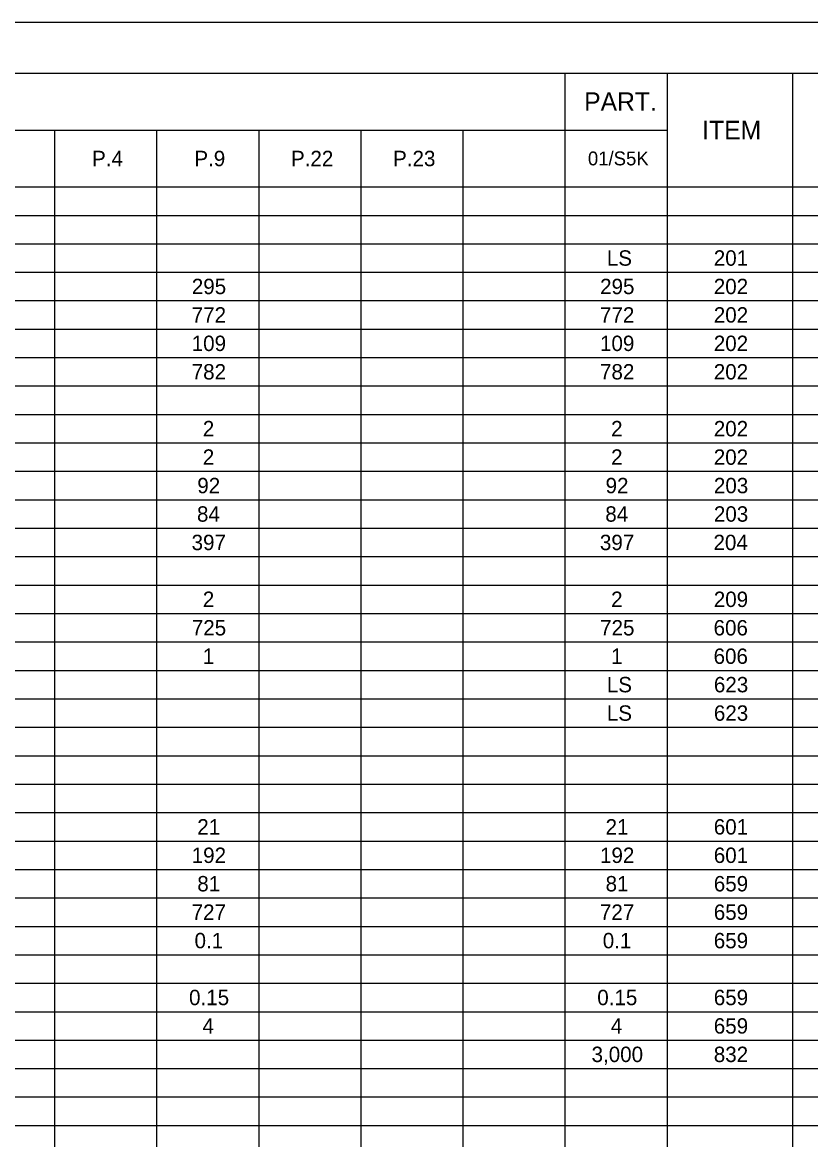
# Model space of a CAD drawing. Extents: x 0 to 34, y 0 to 22.
# Drawn here: x 9.22 to 16.98, y 11 to 22 of the extents above; entities that cross this region are included whole.
import ezdxf

# ---------------------------------------------------------------- set-up
doc = ezdxf.new("R2010")
doc.units = 0
for name, color, linetype in [('Default', 7, 'Continuous'), ('SH_Border', 7, 'Continuous'), ('SH_Cut_Line', 7, 'Continuous')]:
    doc.layers.add(name, color=color, linetype=linetype)

msp = doc.modelspace()

# ---------------------------------------------------------------- linework, layer by layer
at = {"layer": 'Default'}
for p, q in [((1.5, 21.5), (32.004, 21.5)), ((14.561, 21.5), (14.561, 0.5)), ((15.566, 21.5), (15.566, 0.5)), ((16.801, 21.5), (16.801, 0.5)), ((1.5, 20.94), (15.566, 20.94)), ((9.538, 20.94), (9.538, 0.5)), ((10.542, 20.94), (10.542, 0.5)), ((11.547, 20.94), (11.547, 0.5)), ((12.552, 20.94), (12.552, 0.5)), ((13.556, 20.94), (13.556, 0.5)), ((1.5, 20.38), (32.004, 20.38)), ((1.5, 20.1), (32.004, 20.1)), ((1.5, 19.82), (32.004, 19.82)), ((1.5, 19.54), (32.004, 19.54)), ((1.5, 19.26), (32.004, 19.26)), ((1.5, 18.98), (32.004, 18.98)), ((1.5, 18.7), (32.004, 18.7)), ((1.5, 18.42), (32.004, 18.42)), ((1.5, 18.14), (32.004, 18.14)), ((1.5, 17.86), (32.004, 17.86)), ((1.5, 17.58), (32.004, 17.58)), ((1.5, 17.3), (32.004, 17.3)), ((1.5, 17.02), (32.004, 17.02)), ((1.5, 16.74), (32.004, 16.74)), ((1.5, 16.46), (32.004, 16.46)), ((1.5, 16.18), (32.004, 16.18)), ((1.5, 15.9), (32.004, 15.9)), ((1.5, 15.62), (32.004, 15.62)), ((1.5, 15.34), (32.004, 15.34)), ((1.5, 15.06), (32.004, 15.06)), ((1.5, 14.78), (32.004, 14.78)), ((1.5, 14.5), (32.004, 14.5)), ((1.5, 14.22), (32.004, 14.22)), ((1.5, 13.94), (32.004, 13.94)), ((1.5, 13.66), (32.004, 13.66)), ((1.5, 13.38), (32.004, 13.38)), ((1.5, 13.1), (32.004, 13.1)), ((1.5, 12.82), (32.004, 12.82)), ((1.5, 12.54), (32.004, 12.54)), ((1.5, 12.26), (32.004, 12.26)), ((1.5, 11.98), (32.004, 11.98)), ((1.5, 11.7), (32.004, 11.7)), ((1.5, 11.42), (32.004, 11.42)), ((1.5, 11.14), (32.004, 11.14))]:
    msp.add_line(p, q, dxfattribs=at)
at = {"layer": 'SH_Border'}
msp.add_lwpolyline([(1.5, 21.5), (33.5, 21.5), (33.5, 0.5), (1.5, 0.5)], close=True, dxfattribs=at)
at = {"layer": 'SH_Cut_Line'}
msp.add_lwpolyline([(0, 0), (34, 0), (34, 22), (0, 22)], close=True, dxfattribs=at)

# ---------------------------------------------------------------- texts
at = {"layer": 'Default'}
for s, height, p in [('PART.', 0.1818, (14.75, 21.129)), ('ITEM', 0.1818, (15.912, 20.849)), ('P.4', 0.1515, (9.906, 20.584)), ('P.9', 0.1515, (10.913, 20.584)), ('P.22', 0.1515, (11.864, 20.584)), ('P.23', 0.1515, (12.869, 20.584)), ('01/S5K', 0.1364, (14.787, 20.592)), ('LS', 0.1515, (14.973, 19.604)), ('201', 0.1515, (16.026, 19.604)), ('295', 0.1515, (10.888, 19.324)), ('295', 0.1515, (14.907, 19.324)), ('202', 0.1515, (16.026, 19.324)), ('772', 0.1515, (10.887, 19.044)), ('772', 0.1515, (14.906, 19.044)), ('202', 0.1515, (16.026, 19.044)), ('109', 0.1515, (10.887, 18.764)), ('109', 0.1515, (14.906, 18.764)), ('202', 0.1515, (16.026, 18.764)), ('782', 0.1515, (10.887, 18.484)), ('782', 0.1515, (14.906, 18.484)), ('202', 0.1515, (16.026, 18.484)), ('2', 0.152, (10.996, 17.924)), ('2', 0.152, (15.015, 17.924)), ('202', 0.1515, (16.026, 17.924)), ('2', 0.152, (10.996, 17.644)), ('2', 0.152, (15.015, 17.644)), ('202', 0.1515, (16.026, 17.644)), ('92', 0.1515, (10.942, 17.364)), ('92', 0.1515, (14.961, 17.364)), ('203', 0.1515, (16.027, 17.364)), ('84', 0.1515, (10.939, 17.084)), ('84', 0.1515, (14.958, 17.084)), ('203', 0.1515, (16.027, 17.084)), ('397', 0.1515, (10.886, 16.804)), ('397', 0.1515, (14.905, 16.804)), ('204', 0.1515, (16.023, 16.804)), ('2', 0.152, (10.996, 16.244)), ('2', 0.152, (15.015, 16.244)), ('209', 0.1515, (16.026, 16.244)), ('725', 0.1515, (10.888, 15.964)), ('725', 0.1515, (14.907, 15.964)), ('606', 0.1515, (16.024, 15.964)), ('1', 0.152, (10.996, 15.684)), ('1', 0.152, (15.015, 15.684)), ('606', 0.1515, (16.024, 15.684)), ('LS', 0.1515, (14.973, 15.404)), ('623', 0.1515, (16.027, 15.404)), ('LS', 0.1515, (14.973, 15.124)), ('623', 0.1515, (16.027, 15.124)), ('21', 0.1515, (10.942, 14.004)), ('21', 0.1515, (14.961, 14.004)), ('601', 0.1515, (16.026, 14.004)), ('192', 0.1515, (10.887, 13.724)), ('192', 0.1515, (14.906, 13.724)), ('601', 0.1515, (16.026, 13.724)), ('81', 0.1515, (10.942, 13.444)), ('81', 0.1515, (14.961, 13.444)), ('659', 0.1515, (16.026, 13.444)), ('727', 0.1515, (10.886, 13.164)), ('727', 0.1515, (14.905, 13.164)), ('659', 0.1515, (16.026, 13.164)), ('0.1', 0.1515, (10.915, 12.884)), ('0.1', 0.1515, (14.933, 12.884)), ('659', 0.1515, (16.026, 12.884)), ('0.15', 0.1515, (10.861, 12.324)), ('0.15', 0.1515, (14.879, 12.324)), ('659', 0.1515, (16.026, 12.324)), ('4', 0.152, (10.993, 12.044)), ('4', 0.152, (15.012, 12.044)), ('659', 0.1515, (16.026, 12.044)), ('3,000', 0.1515, (14.823, 11.764)), ('832', 0.1515, (16.026, 11.764))]:
    msp.add_text(s, height=height, dxfattribs=at).set_placement(p)

doc.saveas('drawing.dxf')
